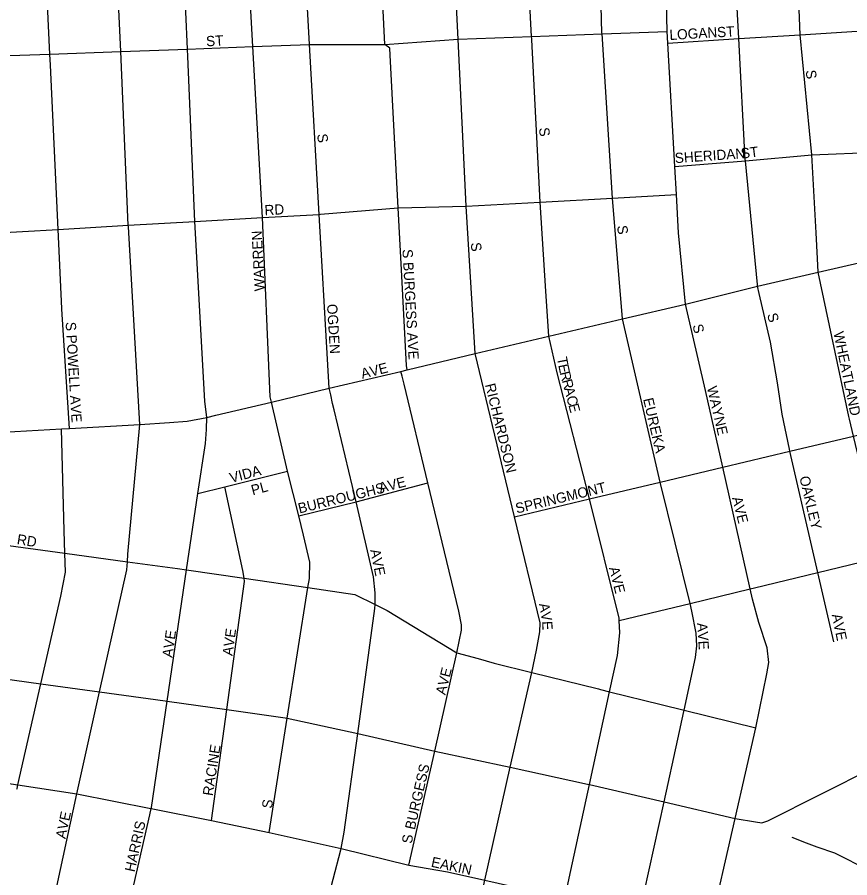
# Model space of a CAD drawing. Extents: x 0 to 34, y -6.2 to 22.
# Drawn here: x 2.696 to 3.469, y 16.379 to 17.178 of the extents above; entities that cross this region are included whole.
import ezdxf

# ---------------------------------------------------------------- set-up
doc = ezdxf.new("R2010")
doc.units = 0
for name, color, linetype in [('GM_X_City_Street', 7, 'Continuous'), ('GM_X_City_Street_Text', 7, 'Continuous'), ('GM_X_Minor_River', 7, 'Continuous')]:
    doc.layers.add(name, color=color, linetype=linetype)

msp = doc.modelspace()

# ---------------------------------------------------------------- linework, layer by layer
at = {"layer": 'GM_X_City_Street'}
for points in [[(3.43904, 16.9539), (3.43765, 16.97757), (3.43378, 17.05), (3.42307, 17.16142), (3.41483, 17.36724), (3.41064, 17.47189), (3.40679, 17.56795), (3.40468, 17.61182)], [(3.38323, 16.92973), (3.37207, 17.0445), (3.37203, 17.04518), (3.36591, 17.15775), (3.35882, 17.28808), (3.35629, 17.33474), (3.35546, 17.36288), (3.35388, 17.38749), (3.35057, 17.4391), (3.34876, 17.46728), (3.34725, 17.49083), (3.34831, 17.54929), (3.34687, 17.57568), (3.34575, 17.60802)], [(3.27368, 16.34478), (3.29673, 16.4497), (3.30954, 16.50801), (3.315, 16.53353), (3.31528, 16.53481), (3.32593, 16.58379), (3.32697, 16.59444), (3.32648, 16.60621), (3.3225, 16.6267), (3.32074, 16.63388), (3.29313, 16.7464), (3.25795, 16.89783), (3.24882, 17.00989), (3.23911, 17.16213), (3.23906, 17.16288), (3.23518, 17.3149), (3.22829, 17.42881), (3.22212, 17.56473), (3.2207, 17.60083)], [(3.12582, 16.35982), (3.12602, 16.36031), (3.12718, 16.36323), (3.1303, 16.37705), (3.15398, 16.48197), (3.17382, 16.56986), (3.17844, 16.59036), (3.18149, 16.60756), (3.18168, 16.61593), (3.15792, 16.7142), (3.1215, 16.86577), (3.11952, 16.89635), (3.11304, 17.00234), (3.1055, 17.15726), (3.09863, 17.29851), (3.09286, 17.41697), (3.08623, 17.55807), (3.08431, 17.59258)], [(2.93207, 16.82185), (2.93123, 16.82537), (2.92403, 16.99174), (2.92402, 16.99195), (2.91522, 17.15034), (2.90749, 17.28957), (2.90102, 17.4059), (2.89532, 17.53927), (2.89128, 17.58135)], [(2.99061, 16.8133), (2.98915, 16.81942), (2.98743, 16.82731), (2.98595, 16.83348), (2.98425, 16.86051), (2.97667, 16.99475), (2.96777, 17.15225), (2.95987, 17.29202), (2.95328, 17.40892), (2.95099, 17.52321), (2.95034, 17.5367), (2.94793, 17.58603)], [(2.73784, 16.90667), (2.73779, 16.90749), (2.73437, 16.98086), (2.72728, 17.13321), (2.72678, 17.14348), (2.72357, 17.20939), (2.7201, 17.2808), (2.71445, 17.39684), (2.70761, 17.53747), (2.706, 17.57057)], [(2.81015, 16.79978), (2.81015, 16.79978), (2.79959, 16.98332), (2.79954, 16.9846), (2.79255, 17.14587), (2.79059, 17.19114), (2.78596, 17.28388), (2.78119, 17.40008), (2.77449, 17.53297), (2.77409, 17.54015), (2.77221, 17.57666)], [(2.87213, 16.79548), (2.87229, 16.80641), (2.87069, 16.8216), (2.86134, 16.98814), (2.85472, 17.1411), (2.8544, 17.14812), (2.84814, 17.28679), (2.84289, 17.40308), (2.83557, 17.53618), (2.83498, 17.57808)], [(3.04255, 17.14233), (3.04219, 17.14906), (3.03741, 17.15222), (3.03028, 17.30363), (3.02436, 17.41162)], [(3.17386, 17.15779), (3.17376, 17.15975), (3.16626, 17.30218), (3.16025, 17.4165), (3.16018, 17.41784)], [(3.33825, 16.32736), (3.36258, 16.4344), (3.3817, 16.51834), (3.3921, 16.56843), (3.3939, 16.5791), (3.39226, 16.59276), (3.38446, 16.61625), (3.37857, 16.63785), (3.37644, 16.64731), (3.35105, 16.76018), (3.33506, 16.83126), (3.31648, 16.91147), (3.3102, 16.97771), (3.30815, 17.01318), (3.30664, 17.03928), (3.30004, 17.15352), (3.29942, 17.16433), (3.29682, 17.28631)], [(2.60379, 17.139), (2.60381, 17.139), (2.6614, 17.1411), (2.72678, 17.14348), (2.79255, 17.14587), (2.8544, 17.14812), (2.91522, 17.15034), (2.96777, 17.15225), (3.03741, 17.15222), (3.1055, 17.15726), (3.17376, 17.15975), (3.23911, 17.16213), (3.29942, 17.16433)], [(3.30004, 17.15352), (3.36591, 17.15775), (3.42307, 17.16142), (3.48556, 17.16543)], [(3.20453, 16.36034), (3.22737, 16.4658), (3.24604, 16.55197), (3.25332, 16.58561), (3.25573, 16.60645), (3.25505, 16.61804), (3.25493, 16.62015), (3.22734, 16.73073), (3.19762, 16.84785), (3.18989, 16.88188), (3.1871, 16.92348), (3.18183, 17.00616), (3.17392, 17.15656), (3.17386, 17.15779)], [(3.05817, 16.8504), (3.05768, 16.85461), (3.05312, 16.94339), (3.04995, 17.0009), (3.04255, 17.14233)], [(3.30664, 17.03928), (3.37207, 17.0445), (3.43378, 17.05), (3.49395, 17.05246)], [(2.6151, 16.97403), (2.66803, 16.97706), (2.73437, 16.98086), (2.79954, 16.9846), (2.86134, 16.98814), (2.92403, 16.99174), (2.97667, 16.99475), (2.97789, 16.99482), (3.04995, 17.0009), (3.11304, 17.00234), (3.18183, 17.00616), (3.24882, 17.00989), (3.30815, 17.01318)], [(2.67239, 16.79224), (2.7375, 16.79567), (2.74492, 16.79612), (2.81015, 16.79978), (2.83791, 16.80161), (2.85424, 16.80298), (2.87229, 16.80641), (2.88085, 16.80846), (2.93237, 16.82057), (2.98595, 16.83348), (3.0524, 16.84896), (3.05817, 16.8504), (3.1215, 16.86577), (3.18989, 16.88188), (3.25795, 16.89783), (3.31648, 16.91147), (3.38339, 16.92808), (3.43978, 16.94123), (3.5002, 16.95498)], [(3.46821, 16.80723), (3.43978, 16.94123), (3.43904, 16.9539)], [(3.15792, 16.7142), (3.22734, 16.73073), (3.29313, 16.7464), (3.35105, 16.76018), (3.41343, 16.77504), (3.4725, 16.7891), (3.53224, 16.80333), (3.62273, 16.82487), (3.72953, 16.8503), (3.78317, 16.86307), (3.84332, 16.87739), (3.89883, 16.89061), (3.95436, 16.90383), (4.00704, 16.91637), (4.00779, 16.91658), (4.06096, 16.93101), (4.0624, 16.93132), (4.06645, 16.93219)], [(3.45419, 16.59816), (3.43937, 16.66248), (3.41343, 16.77504), (3.41297, 16.77703), (3.40617, 16.8095), (3.40194, 16.83848), (3.3954, 16.87613), (3.38487, 16.92134), (3.38339, 16.92808), (3.38323, 16.92973)], [(2.74492, 16.79612), (2.73784, 16.90667)], [(3.05998, 16.39095), (3.08399, 16.49685), (3.1044, 16.58795), (3.10873, 16.60916), (3.10864, 16.61404), (3.10611, 16.62677), (3.0774, 16.74576), (3.05558, 16.83712), (3.05357, 16.84456), (3.0524, 16.84896)], [(2.93022, 16.42125), (2.94702, 16.52741), (2.96619, 16.64848), (2.96751, 16.65684), (2.96788, 16.67204), (2.96204, 16.69726), (2.95764, 16.71498), (2.94734, 16.75651), (2.93237, 16.82057), (2.93207, 16.82185)], [(2.98264, 16.35074), (2.9967, 16.4053), (2.99695, 16.40657), (2.99976, 16.42157), (3.01237, 16.51308), (3.02837, 16.62912), (3.02846, 16.63274), (3.02872, 16.64356), (3.02719, 16.65842), (3.01097, 16.72809), (2.99061, 16.8133)], [(3.54051, 16.50645), (3.49948, 16.67698), (3.4725, 16.7891), (3.46871, 16.8049), (3.46821, 16.80723)], [(2.7729, 16.55191), (2.7729, 16.55191), (2.79824, 16.66511), (2.79871, 16.67253), (2.79916, 16.67953), (2.81015, 16.79978)], [(2.69618, 16.46155), (2.69633, 16.46222), (2.69708, 16.46553), (2.71846, 16.55939), (2.73692, 16.64046), (2.74126, 16.66277), (2.74064, 16.68045), (2.73992, 16.70119), (2.7375, 16.79567)], [(2.81948, 16.43774), (2.82079, 16.44351), (2.82103, 16.44457), (2.83564, 16.54326), (2.85366, 16.66496), (2.86416, 16.73586), (2.87105, 16.78234), (2.87212, 16.79523), (2.87213, 16.79548)], [(2.86416, 16.73586), (2.88921, 16.74208), (2.94734, 16.75651)], [(2.87661, 16.43239), (2.89094, 16.53547), (2.90743, 16.65413), (2.90695, 16.65715), (2.90578, 16.66444), (2.88921, 16.74208)], [(2.95764, 16.71498), (3.01097, 16.72809), (3.0774, 16.74576)], [(3.38058, 16.64831), (3.38067, 16.64833), (3.43937, 16.66248), (3.49948, 16.67698), (3.55839, 16.69118), (3.64751, 16.71267), (3.74753, 16.73678)], [(2.41338, 16.69991), (2.48243, 16.70338), (2.54324, 16.70644), (2.54813, 16.70669), (2.6116, 16.69804), (2.67445, 16.68947), (2.74064, 16.68045), (2.79871, 16.67253), (2.84522, 16.66619), (2.85366, 16.66496), (2.90695, 16.65715), (2.96619, 16.64848), (3.00962, 16.64212), (3.02846, 16.63274), (3.03961, 16.62719), (3.1044, 16.58795), (3.12424, 16.58268), (3.13916, 16.57845), (3.17382, 16.56986), (3.23594, 16.55447), (3.23777, 16.55402)], [(3.25505, 16.61804), (3.32074, 16.63388), (3.37644, 16.64731), (3.38058, 16.64831)], [(2.7729, 16.55191), (2.8337, 16.54354), (2.83564, 16.54326), (2.89094, 16.53547), (2.94504, 16.52784), (2.94702, 16.52741), (3.01237, 16.51308), (3.08399, 16.49685), (3.15398, 16.48197), (3.22567, 16.4662), (3.22737, 16.4658), (3.29673, 16.4497), (3.36258, 16.4344), (3.38159, 16.43116), (3.38728, 16.43045), (3.39296, 16.43202), (3.54051, 16.50645), (3.598, 16.52567), (3.62316, 16.53408), (3.68606, 16.55587), (3.78545, 16.5903)], [(2.53811, 16.58384), (2.53815, 16.58383), (2.53816, 16.58383), (2.59811, 16.57595), (2.60021, 16.57566), (2.65803, 16.56771), (2.71846, 16.55939), (2.7729, 16.55191)], [(2.66856, 16.07037), (2.66859, 16.07053), (2.6758, 16.10297), (2.6917, 16.1781), (2.71187, 16.27344), (2.72379, 16.32828), (2.75181, 16.45725), (2.7729, 16.55191)], [(3.23777, 16.55402), (3.24604, 16.55197), (3.294, 16.54009), (3.31528, 16.53481), (3.3817, 16.51834)], [(2.48531, 16.49643), (2.51845, 16.49173), (2.58033, 16.48293), (2.60844, 16.47894), (2.63668, 16.47467), (2.69708, 16.46553), (2.75181, 16.45725)], [(2.75181, 16.45725), (2.82035, 16.4436)], [(2.69685, 15.899), (2.75714, 16.16389), (2.79237, 16.31868), (2.81947, 16.43771), (2.81948, 16.43774)], [(2.82035, 16.4436), (2.82079, 16.44351), (2.82087, 16.4435), (2.87661, 16.43239), (2.90811, 16.42612), (2.93022, 16.42125), (2.99695, 16.40657), (3.05998, 16.39095), (3.09568, 16.38484), (3.1303, 16.37705), (3.20453, 16.36034), (3.27368, 16.34478), (3.27531, 16.34441), (3.32823, 16.33089), (3.33654, 16.32852), (3.33666, 16.32844)]]:
    msp.add_lwpolyline(points, dxfattribs=at)
at = {"layer": 'GM_X_Minor_River'}
msp.add_lwpolyline([(3.47709, 16.39113), (3.46505, 16.39737), (3.45526, 16.40206), (3.43866, 16.40761), (3.42886, 16.41154), (3.41566, 16.41665)], dxfattribs=at)

# ---------------------------------------------------------------- texts
at = {"layer": 'GM_X_City_Street_Text'}
for s, height, rotation, p in [('LOGAN', 0.00947, 3.50607, (3.30197, 17.1564)), ('ST', 0.00947, 3.57463, (3.34614, 17.1589)), ('ST', 0.00947, 3.58824, (2.87197, 17.15056)), ('S', 0.00947, 277.12166, (3.42802, 17.12817)), ('S', 0.00947, 277.1183, (2.97468, 17.06901)), ('S', 0.00947, 277.1183, (3.18052, 17.07484)), ('SHERIDAN', 0.00947, 4.0834, (3.30695, 17.04223)), ('ST', 0.00947, 7.1351, (3.36853, 17.04639)), ('RD', 0.00947, 3.02245, (2.92615, 16.99389)), ('S', 0.00947, 277.12166, (3.25302, 16.98401)), ('WARREN', 0.00947, 92.86096, (2.92613, 16.9237)), ('S', 0.00947, 277.12166, (3.11718, 16.96817)), ('S BURGESS AVE', 0.0094697, 273.24002, (3.05386, 16.96222)), ('OGDEN', 0.00947, 273.50163, (2.98386, 16.91139)), ('S', 0.00947, 285.96602, (3.39212, 16.90178)), ('S POWELL AVE', 0.0094697, 273.43386, (2.74136, 16.89473)), ('S', 0.00947, 284.05553, (3.32297, 16.89172)), ('WHEATLAND', 0.00947, 281.69012, (3.45382, 16.88498)), ('T', 0.00947, 280.71531, (3.19717, 16.86161)), ('AVE', 0.00947, 14.03624, (3.01665, 16.84218)), ('E', 0.00947, 281.45676, (3.19843, 16.85492)), ('R', 0.00947, 284.23238, (3.19987, 16.8479)), ('RICHARDSON', 0.00947, 283.76199, (3.13048, 16.83671)), ('R', 0.00947, 284.92641, (3.20174, 16.84051)), ('WAYNE', 0.00947, 283.13368, (3.33632, 16.83419)), ('A', 0.00947, 284.92157, (3.20368, 16.83326)), ('C', 0.00947, 284.93143, (3.20582, 16.82521)), ('EUREKA', 0.00947, 283.1935, (3.27715, 16.82336)), ('E', 0.00947, 284.93724, (3.20776, 16.81796)), ('VIDA', 0.00947, 14.83054, (2.89496, 16.74551)), ('AVE', 0.00947, 14.03624, (3.03332, 16.73635)), ('OAKLEY', 0.00947, 283.29523, (3.42215, 16.75086)), ('PL', 0.00947, 14.93776, (2.91494, 16.7341)), ('BURROUGHS', 0.00947, 13.8761, (2.95835, 16.7172)), ('SPRINGMONT', 0.00947, 13.57068, (3.16, 16.71718)), ('AVE', 0.00947, 284.03625, (3.35964, 16.73172)), ('RD', 0.00947, 351.02147, (2.69569, 16.68888)), ('AVE', 0.00947, 281.69062, (3.02383, 16.68331)), ('AVE', 0.00947, 284.03625, (3.24548, 16.66672)), ('A', 0.00947, 280.52969, (3.18049, 16.63333)), ('V', 0.00947, 280.53342, (3.18201, 16.62514)), ('AVE', 0.00947, 281.68912, (3.45216, 16.62331)), ('E', 0.00947, 272.78738, (3.18349, 16.61728)), ('A', 0.00947, 274.44061, (3.32719, 16.6156)), ('AVE', 0.00947, 81.87426, (2.84032, 16.58321)), ('AVE', 0.00947, 82.14336, (2.89615, 16.58486)), ('V', 0.00947, 274.45106, (3.32784, 16.60729)), ('E', 0.00947, 273.06162, (3.32848, 16.59904)), ('AVE', 0.00947, 75.96375, (3.09368, 16.54839)), ('RACINE', 0.00947, 81.08613, (2.87782, 16.45489)), ('BURGESS', 0.00947, 77.07422, (3.06534, 16.42335)), ('S', 0.00947, 82.8817, (2.93281, 16.44317)), ('AVE', 0.00947, 77.90417, (2.74117, 16.415)), ('HARRIS', 0.00947, 77.59483, (2.80534, 16.38417)), ('S', 0.00947, 82.87834, (3.06281, 16.41067)), ('EAKIN', 0.00947, 348.18157, (3.07995, 16.38966))]:
    msp.add_text(s, height=height, rotation=rotation, dxfattribs=at).set_placement(p)

doc.saveas('drawing.dxf')
